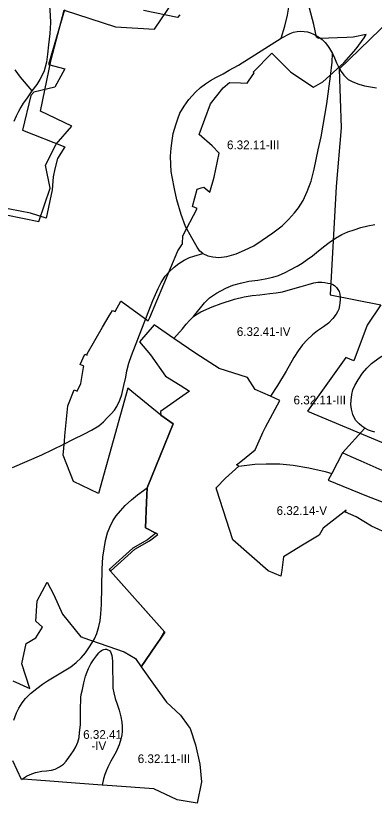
# Model space of a CAD drawing. Extents: x -555156 to -540209, y -1046851 to -1035695.
# Drawn here: x -544168 to -543756, y -1042856 to -1041952 of the extents above; entities that cross this region are included whole.
import ezdxf

# ---------------------------------------------------------------- set-up
doc = ezdxf.new("R2010")
doc.units = 0
for name, color, linetype in [('Vrstva 12', 7, 'Continuous'), ('Vrstva 27', 7, 'Continuous'), ('Vrstva 28', 7, 'Continuous'), ('Vrstva 29', 7, 'Continuous')]:
    doc.layers.add(name, color=color, linetype=linetype)

msp = doc.modelspace()

# ---------------------------------------------------------------- linework, layer by layer
at = {"layer": 'Vrstva 12'}
for points in [[(-544171.15, -1042715.82), (-544151.55, -1042724.51), (-544160.83, -1042696.24), (-544155.75, -1042672.96), (-544144.45, -1042666.13), (-544136.85, -1042654.01), (-544144.5, -1042647.26), (-544142.98, -1042623.77), (-544131.62, -1042602.28), (-544123.71, -1042617.13), (-544113.77, -1042639.15), (-544092.88, -1042664.98), (-544091.08, -1042665.61), (-544090.46, -1042665.82), (-544043.06, -1042682.21), (-544030.21, -1042689.97), (-544023.53, -1042699.54), (-544007.21, -1042675.58), (-544001.87, -1042667.74), (-543996.639614, -1042659.55072), (-544058.8, -1042589.78), (-544030.98, -1042564.71), (-544013.86, -1042554.81), (-544004.309678, -1042547.672849), (-544006.86, -1042546.1), (-544018.75, -1042539.99), (-544017.46, -1042510.83), (-544016.72, -1042494.3), (-543986.75, -1042420.55), (-544001.11, -1042410.51), (-544034.28, -1042383.4), (-544038.85, -1042379.66), (-544072.43, -1042500.56), (-544101.21, -1042486.85), (-544113.33, -1042456.67), (-544111.76, -1042440.57), (-544111.16, -1042434.37), (-544107.72, -1042399.99), (-544100.67, -1042381.51), (-544097.25, -1042383.1), (-544092.94, -1042374.41), (-544089.73, -1042356.05), (-544089.46, -1042354.51), (-544093.47, -1042352.56), (-544088.28, -1042340.62), (-544085.65, -1042341.78), (-544085.63, -1042340.36), (-544067.88, -1042309.81), (-544060.24, -1042296.67), (-544056.67, -1042290.53), (-544053.45, -1042291.6), (-544047.08, -1042279.66), (-544046.53, -1042279.96), (-544015.36585, -1042302.370823), (-544013.52, -1042298.49), (-543981.44, -1042222.13), (-543975.89, -1042214.13), (-543975.6, -1042204.84), (-543959.16, -1042173.35), (-543964.71, -1042171.34), (-543959.3, -1042151.15), (-543954.59, -1042149.85), (-543951.54, -1042148.98), (-543944.53, -1042154.84), (-543939.76, -1042137.53), (-543933.79, -1042109.99), (-543942.18, -1042101.41), (-543956.98, -1042088.32), (-543943.74, -1042053.44), (-543929.51, -1042034.81), (-543922.26, -1042028.69), (-543909.48, -1042029.25), (-543901.85, -1042029.59), (-543895.1, -1042020.15), (-543893.65, -1042018.12), (-543894.94, -1042016.9), (-543873.39, -1041995.26), (-543871.61, -1041997.05), (-543866.3, -1042002.41), (-543851.8, -1042017.03), (-543825.76, -1042034.33), (-543815, -1042028.12), (-543790.82, -1042006.37), (-543776.58, -1041990.04), (-543767.21, -1041977.62), (-543765.06, -1041973.55), (-543780.03, -1041976.76), (-543787.37, -1041977.07), (-543818.99, -1041978.42), (-543820.11, -1041977.82), (-543822.02, -1041976.78), (-543825.08, -1041962.04), (-543835.15, -1041924.24)], [(-544111.61, -1041945.51), (-544130.11, -1042008.16), (-544111.08, -1042013.17), (-544122.64, -1042034.02), (-544138.95, -1042038.08), (-544146.92, -1042040.06), (-544150.25, -1042043.88), (-544159.721498, -1042083.617992), (-544111.17, -1042102.5), (-544119.81, -1042116.14), (-544122.58, -1042127.97), (-544124.69, -1042137.01), (-544125.7, -1042152.16), (-544132.62, -1042184.45), (-544150.62, -1042178.77), (-544186.87, -1042171.92)], [(-543979.22, -1041950.95), (-543981.92, -1041954.13), (-544021.05, -1041946.14)]]:
    msp.add_lwpolyline(points, dxfattribs=at)
at = {"layer": 'Vrstva 28'}
for points in [[(-543862.75, -1041978.07), (-543858.51, -1041964.07), (-543855.54, -1041951.56), (-543853.43, -1041939.9), (-543851.31, -1041925.48), (-543849.4, -1041910.42), (-543848.13, -1041894.31), (-543846.64, -1041875.22), (-543846.58, -1041863.67), (-543846.79, -1041846.49), (-543847.85, -1041825.92), (-543848.27, -1041809.38), (-543848.06, -1041797.08), (-543847.21, -1041787.11), (-543845.31, -1041775.66), (-543842.97, -1041764.85), (-543840.01, -1041755.31), (-543836.62, -1041745.76), (-543832.97, -1041738.45), (-543802.67, -1041692.22), (-543775.11, -1041650.23), (-543757.52, -1041623.94), (-543733.6, -1041589.69)], [(-544152.96, -1041882.3), (-544149.81, -1041890.78), (-544147.02, -1041896.84), (-544144.36, -1041902.29), (-544141.58, -1041907.5), (-544138.2, -1041913.14), (-544133.75, -1041921.2), (-544131.63, -1041927.14), (-544129.93, -1041934.35), (-544128.87, -1041941.35), (-544128.23, -1041951.52), (-544127.81, -1041960.22), (-544128.66, -1041972.73), (-544130.14, -1041985.45), (-544130.99, -1041996.27), (-544132.47, -1042005.39), (-544133.71, -1042011.2), (-544135.17, -1042015.44), (-544136.86, -1042019.44), (-544139.89, -1042025.38), (-544143.31, -1042031.01), (-544149.13, -1042038.53)], [(-543862.75, -1041978.07), (-543852.47, -1041972.68), (-543848.39, -1041971.09), (-543844.3, -1041970.33), (-543840.22, -1041970.05), (-543836.35, -1041970.12)], [(-543836.35, -1041970.12), (-543832.54, -1041970.68), (-543828.87, -1041971.78), (-543825.41, -1041973.24), (-543822.09, -1041975.04), (-543818.56, -1041977.25), (-543815.72, -1041979.4), (-543812.12, -1041982.86), (-543809.5, -1041986.19), (-543807, -1041989.65), (-543804.72, -1041993.46), (-543803.62, -1041995.7)], [(-543952.56, -1042225.28), (-543956.07, -1042222.25), (-543959.31, -1042217.7), (-543965.25, -1042207.31), (-543972.45, -1042193.95), (-543977.54, -1042180.38), (-543982.41, -1042163.42), (-543985.38, -1042150.91), (-543988.02, -1042137), (-543988.98, -1042131.06), (-543989.59, -1042122.95), (-543989.71, -1042113.49), (-543988.98, -1042104.04), (-543987.89, -1042095.2), (-543986.68, -1042087.44), (-543983.78, -1042077.26), (-543981.6, -1042070.6), (-543978.95, -1042064.08), (-543974.1, -1042055.84), (-543968.65, -1042048.33), (-543961.15, -1042040.09), (-543955.45, -1042034.39), (-543949.52, -1042030.27), (-543944.07, -1042026.64), (-543937.89, -1042023.24), (-543929.54, -1042018.88), (-543922.39, -1042014.76), (-543911.91, -1042009.07), (-543862.75, -1041978.07)], [(-543952.56, -1042225.28), (-543947.11, -1042227.7), (-543941.06, -1042229.03), (-543934.4, -1042229.52), (-543925.19, -1042228.55), (-543914.41, -1042225.52), (-543904.72, -1042221.4), (-543894.07, -1042216.31), (-543884.38, -1042209.77), (-543872.15, -1042201.53), (-543861.73, -1042193.29), (-543854.34, -1042186.02), (-543847.32, -1042178.38), (-543842.84, -1042172.66), (-543837.63, -1042164.3), (-543832.79, -1042154), (-543828.43, -1042141.89), (-543824.67, -1042128.44), (-543820.07, -1042106.26), (-543816.92, -1042091.36), (-543810.39, -1042053.26), (-543805.94, -1042021.67), (-543804.24, -1042005.31), (-543803.62, -1041995.7)], [(-543803.62, -1041995.7), (-543802.99, -1041996.99)], [(-543802.99, -1041996.99), (-543801.4, -1042000.66), (-543799.28, -1042006.19), (-543796.98, -1042010.8), (-543793.95, -1042016.01), (-543790.56, -1042020.25), (-543785.59, -1042025.22), (-543780.51, -1042028.13), (-543773.6, -1042030.55), (-543766.94, -1042032.49), (-543760.04, -1042033.94), (-543753.26, -1042034.91)], [(-544168.51, -1042014.1), (-544162.46, -1042022.58), (-544149.13, -1042038.53)], [(-544149.13, -1042038.53), (-544155.42, -1042047.49), (-544158.94, -1042052.7), (-544161.72, -1042056.94), (-544164.63, -1042062.15), (-544167.05, -1042067.36), (-544169.84, -1042073.67)], [(-543963.35, -1042297.38), (-543950.68, -1042281.75), (-543945.11, -1042276.18), (-543937.12, -1042270.48), (-543926.34, -1042264.79), (-543918.23, -1042261.64), (-543909.27, -1042259.21), (-543899.7, -1042256.91), (-543889.4, -1042255.58), (-543881.29, -1042254.36), (-543872.21, -1042252.18), (-543865.91, -1042250.24), (-543858.28, -1042247.09), (-543852.22, -1042243.82), (-543844.35, -1042239.46), (-543838.78, -1042236.07), (-543832.85, -1042231.83), (-543826.91, -1042227.83), (-543821.94, -1042223.96), (-543814.07, -1042217.54), (-543807.53, -1042212.45), (-543800.38, -1042207.6), (-543792.87, -1042203.24), (-543786.09, -1042200.21), (-543778.95, -1042197.78), (-543771.32, -1042195.36), (-543763.08, -1042193.18), (-543755.21, -1042191.73)], [(-544171.26, -1042470.72), (-544137.77, -1042456.3), (-544112.54, -1042443.82), (-544101.89, -1042438.61), (-544088.56, -1042432.31), (-544080.81, -1042428.07), (-544072.34, -1042422.98), (-544067.01, -1042418.38), (-544062.89, -1042414.26), (-544058.05, -1042409.17), (-544054.17, -1042404.81), (-544051.56, -1042400.76), (-544047.96, -1042393.55), (-544045.62, -1042386.98), (-544043.29, -1042376.59), (-544041.17, -1042367.26), (-544039.9, -1042359.84), (-544037.78, -1042351.14), (-544034.6, -1042342.18), (-544010.1, -1042279.17), (-544004.16, -1042265.24), (-544000.77, -1042258.21), (-543995.93, -1042251.3), (-543991.33, -1042246.09), (-543985.76, -1042240.64), (-543980.43, -1042236.64), (-543974.13, -1042232.64), (-543967.95, -1042229.85), (-543962.87, -1042228.28), (-543952.56, -1042225.28)], [(-543963.35, -1042297.38), (-543958.92, -1042294.26), (-543955.08, -1042292.26), (-543941.88, -1042286.32), (-543931.71, -1042282.44), (-543916.45, -1042277.59), (-543905.18, -1042274.93), (-543895.98, -1042273.23), (-543887.14, -1042272.38), (-543875.76, -1042271.17), (-543868.61, -1042270.08), (-543861.34, -1042269.03), (-543849.3, -1042265.57), (-543839.61, -1042263.01), (-543831.72, -1042260.52), (-543825.22, -1042258.92), (-543820.51, -1042258.16), (-543815.94, -1042258.16), (-543812.62, -1042258.37)], [(-543812.62, -1042258.37), (-543808.95, -1042258.99), (-543806.18, -1042259.62), (-543803.55, -1042260.59), (-543801.27, -1042261.97), (-543799.06, -1042264.05), (-543797.46, -1042266.26), (-543796.22, -1042268.83), (-543795.46, -1042271.6), (-543794.97, -1042275.4), (-543795.04, -1042278.45), (-543795.18, -1042281.64), (-543795.6, -1042284.75), (-543796.63, -1042288.84), (-543797.81, -1042291.88), (-543799.4, -1042294.93), (-543803.28, -1042299.9), (-543808.49, -1042304.99), (-543814.06, -1042309.23), (-543820.84, -1042313.95), (-543826.89, -1042318.56), (-543832.83, -1042324.13), (-543838.16, -1042329.95), (-543843.24, -1042336.98), (-543848.21, -1042344.61), (-543857.12, -1042360.01), (-543866.87, -1042376.69), (-543874.9, -1042389.04)], [(-543986.21, -1042322.51), (-543976.23, -1042311.61), (-543971.72, -1042306.38), (-543967.64, -1042301.81), (-543963.35, -1042297.38)], [(-543986.21, -1042322.51), (-544008.72, -1042307.15), (-544025.54, -1042326.58), (-544012.94, -1042341.62), (-543995.73, -1042365.92), (-543978.69, -1042376.44), (-543968.12, -1042382.96), (-544001.39, -1042406.57), (-544001.11, -1042410.51), (-543986.75, -1042420.55), (-544016.72, -1042494.3)], [(-543874.9, -1042389.04), (-543892.62, -1042381.13), (-543901.36, -1042367.58), (-543933.95, -1042357.29), (-543960.63, -1042339.97), (-543986.21, -1042322.51)], [(-543766.5, -1042425.67), (-543770.1, -1042423.18), (-543773.22, -1042420.48), (-543776.82, -1042416.74), (-543779.24, -1042412.79), (-543780.35, -1042409.74), (-543781.94, -1042403.72), (-543782.7, -1042398.6), (-543782.49, -1042393.54), (-543781.53, -1042386.85), (-543780.2, -1042381.52), (-543778.14, -1042376.55), (-543774.14, -1042370.25), (-543769.18, -1042362.37), (-543764.33, -1042356.56), (-543759, -1042351.47), (-543750.16, -1042344.8), (-543739.87, -1042338.38), (-543729.33, -1042333.41), (-543723.62, -1042331.97), (-543716.84, -1042330.76), (-543704.6, -1042329.79), (-543695.4, -1042329.79)], [(-543911.35, -1042469.41), (-543914, -1042467.7), (-543909.21, -1042463.84), (-543892.75, -1042450.56), (-543884.95, -1042433.37), (-543883.76, -1042430.75), (-543880.86, -1042424.34), (-543864.22, -1042393.81), (-543874.9, -1042389.04)], [(-543792.12, -1042454.05), (-543766.5, -1042425.67)], [(-543755.09, -1042430.03), (-543758.82, -1042428.92), (-543762.28, -1042427.75), (-543766.5, -1042425.67)], [(-543792.12, -1042454.05), (-543804.68, -1042477.58)], [(-543739.84, -1042477.33), (-543770.99, -1042463.46), (-543782.33, -1042458.41), (-543792.12, -1042454.05)], [(-543911.35, -1042469.41), (-543892.94, -1042466.97), (-543879.86, -1042466.37), (-543864.12, -1042466.61)], [(-543864.12, -1042466.61), (-543848.86, -1042468.18), (-543831.06, -1042471.33), (-543812.16, -1042475.45), (-543804.68, -1042477.58)], [(-543715.46, -1042558.09), (-543758.78, -1042538.26), (-543776.4, -1042527.24), (-543789, -1042522.19), (-543788.02, -1042519.68), (-543790.47, -1042521.6), (-543814.33, -1042540.29), (-543819.25, -1042548.35), (-543838.28, -1042560.08), (-543859.89, -1042573.41), (-543862.09, -1042588.69), (-543863.06, -1042595.46), (-543877.78, -1042589.27), (-543918.07, -1042553.94), (-543936.6, -1042496.61), (-543937.33, -1042493.98), (-543926.67, -1042483.2), (-543911.35, -1042469.41)], [(-543804.68, -1042477.58), (-543808.73, -1042485.17), (-543764.69, -1042503.24), (-543697.04, -1042529.44)], [(-544170.01, -1042760.88), (-544166.86, -1042752.28), (-544163.95, -1042746.95), (-544160.44, -1042741.01), (-544156.32, -1042736.04), (-544150.75, -1042730.23), (-544143.6, -1042724.41), (-544136.82, -1042719.32), (-544131.24, -1042715.67), (-544115.74, -1042706.46), (-544104.35, -1042699.55), (-544098.3, -1042694.59), (-544092.6, -1042689.13), (-544087.52, -1042683.44), (-544082.19, -1042675.68), (-544077.22, -1042667.32), (-544074.56, -1042661.51), (-544072.26, -1042653.39), (-544070.8, -1042646.97), (-544069.84, -1042638.73), (-544069.01, -1042628.06), (-544068.38, -1042586.93), (-544067.56, -1042573.57), (-544066.11, -1042564.24), (-544064.53, -1042554.54), (-544062.23, -1042545.7), (-544059.57, -1042539.15), (-544056.06, -1042532.13), (-544052.18, -1042526.31), (-544047.34, -1042520.37), (-544041.77, -1042514.31), (-544034.5, -1042507.89), (-544027.6, -1042502.32), (-544016.72, -1042494.3)], [(-544016.72, -1042494.3), (-544017.46, -1042510.83)], [(-544017.46, -1042510.83), (-544018.75, -1042539.99), (-544006.86, -1042546.1), (-544016.14, -1042553.71), (-544032.97, -1042563.33), (-544060.37, -1042588.02), (-544058.8, -1042589.78), (-543996.4, -1042659.82), (-544001.87, -1042667.74), (-544007.21, -1042675.58), (-544023.53, -1042699.54), (-544007.6, -1042722.34), (-543994.35, -1042740.08), (-543978.53, -1042755.27), (-543969.68, -1042767.22), (-543967.35, -1042770.36), (-543961.17, -1042789.27), (-543956.03, -1042811.37), (-543954.4, -1042831.58), (-543959.26, -1042856.2), (-543982.29, -1042852.21), (-544009.18, -1042839.83), (-544057.02, -1042836.26), (-544068.37, -1042835.41)], [(-544161.17, -1042828.79), (-544155.16, -1042824.95), (-544150.92, -1042823.02), (-544144.86, -1042820.83), (-544137.84, -1042819.38), (-544132.27, -1042818.9), (-544126.45, -1042818.29), (-544122.46, -1042817.08), (-544117.49, -1042814.53), (-544112.89, -1042811.26), (-544109.86, -1042807.82), (-544106.47, -1042803.66), (-544101.28, -1042796.18), (-544098.48, -1042791.31), (-544096.3, -1042786.22), (-544094.97, -1042780.89), (-544094.24, -1042774.95), (-544093.39, -1042766.22), (-544093.27, -1042757.26), (-544093.15, -1042745.63), (-544093, -1042738.56), (-544092.8, -1042734.75), (-544092.31, -1042731.5), (-544091.07, -1042725.55), (-544089.4, -1042717.79), (-544087.33, -1042710.45), (-544085.74, -1042705.37), (-544084.15, -1042701.49), (-544081.38, -1042696.23), (-544078.34, -1042691.73), (-544074.94, -1042686.95), (-544072.11, -1042683.42), (-544070.59, -1042682.13), (-544069.04, -1042681.03), (-544067.58, -1042680.08), (-544066.35, -1042679.52), (-544064.77, -1042679.33), (-544063.27, -1042679.48)], [(-544063.27, -1042679.48), (-544061.73, -1042680), (-544060.03, -1042681.03), (-544058.84, -1042682.21), (-544057.85, -1042684.19), (-544057.22, -1042686.49), (-544056.94, -1042689.3), (-544056.63, -1042693.57), (-544056.67, -1042699.5), (-544056.29, -1042718.62), (-544055.93, -1042724.05), (-544055.08, -1042729.5), (-544053.38, -1042735.8), (-544051.08, -1042742.47), (-544048.78, -1042749.49), (-544046.84, -1042756.88), (-544045.87, -1042763.06), (-544045.27, -1042768.28), (-544045.46, -1042773.82), (-544045.95, -1042777.83), (-544046.92, -1042782.61), (-544048.99, -1042789.33), (-544052.45, -1042797.22), (-544058.41, -1042808.08), (-544061.68, -1042814.74), (-544063.76, -1042819.35), (-544065.21, -1042823.37), (-544066.74, -1042828.21), (-544068.37, -1042835.41)], [(-544161.17, -1042828.79), (-544171.14, -1042807.57)], [(-544068.37, -1042835.41), (-544099.01, -1042833.12), (-544133.37, -1042830.56), (-544149.26, -1042829.37), (-544158.87, -1042828.65), (-544161.17, -1042828.79)]]:
    msp.add_lwpolyline(points, dxfattribs=at)
at = {"layer": 'Vrstva 29'}
for points in [[(-543678.559001, -1041899.701006), (-543737.071999, -1041956.557991), (-543796.091003, -1042013.368007), (-543793.823995, -1042080.887994), (-543799.702006, -1042148.137997), (-543806.402996, -1042272.415009), (-543748.249997, -1042283.844996), (-543763.8451, -1042307.420507), (-543779.24, -1042348.49), (-543788.573719, -1042344.469722), (-543832.654991, -1042406.291991), (-543747.419006, -1042441.730009), (-543646.369004, -1042488.114995), (-543571.098993, -1042518.264998), (-543487.431992, -1042513.782999), (-543418.474993, -1042516.304998), (-543330.975997, -1042544.056998), (-543226.944, -1042575.176006), (-543180.376133, -1042486.397776)], [(-544235.268005, -1042169.153015), (-544141.085999, -1042188.367004), (-544128.255981, -1042150.080994), (-544133.651978, -1042123.560913), (-544121.153992, -1042099.518005), (-544103.124023, -1042079.065002), (-544139.278015, -1042061.836975), (-544126.985901, -1042002.338989), (-544112.174988, -1041945.887024), (-544052.971008, -1041965.065979), (-544008.268005, -1041967.560974), (-543985.653015, -1041933.781006)]]:
    msp.add_lwpolyline(points, dxfattribs=at)

# ---------------------------------------------------------------- texts
at = {"layer": 'Vrstva 27'}
for s, p in [('6.32.11-III', (-543924.966548, -1042105.37)), ('6.32.41-IV', (-543913.677241, -1042319.76)), ('6.32.11-III', (-543848.516548, -1042398.32)), ('6.32.14-V', (-543867.980884, -1042525.19)), ('6.32.41', (-544090.183394, -1042782.25)), ('-IV', (-544080.753462, -1042795.25)), ('6.32.11-III', (-544027.476548, -1042810.09))]:
    msp.add_text(s, height=10, dxfattribs=at).set_placement(p)

doc.saveas('drawing.dxf')
